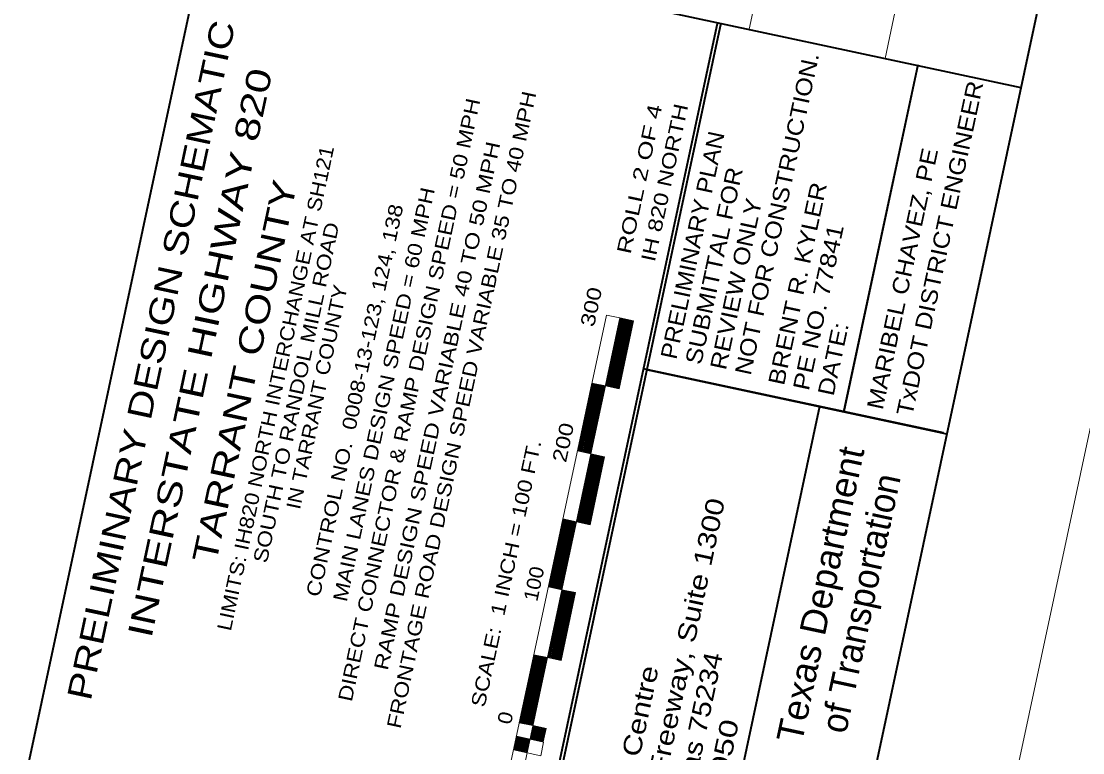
# Model space of a CAD drawing. Extents: x 2363411 to 2369126, y 6976878 to 6988319.
# Drawn here: x 2366272 to 2367036, y 6977474 to 6978000 of the extents above; entities that cross this region are included whole.
import ezdxf
from ezdxf.enums import TextEntityAlignment as Align

# ---------------------------------------------------------------- set-up
doc = ezdxf.new("R2010")
doc.units = 0
doc.header["$LTSCALE"] = 2
for name, color, linetype, lineweight in [('40', 7, 'Continuous', 13), ('62', 7, 'Continuous', 13), ('63', 7, 'Continuous', 13)]:
    doc.layers.add(name, color=color, linetype=linetype, lineweight=lineweight)
doc.layers.add('61', color=7, linetype='Continuous')

msp = doc.modelspace()

# ---------------------------------------------------------------- linework, layer by layer
at = {"layer": '40'}
for p, q in [((2368675.884, 6986794.415), (2366795.645, 6977994.623)), ((2368773.68, 6986773.519), (2366893.442, 6977973.727))]:
    msp.add_line(p, q, dxfattribs=at)
at = {"layer": '62'}
for p, q in [((2369126.202, 6987466.173), (2366932.108, 6977197.487)), ((2366609.253, 6977397.699), (2366692.845, 6977788.923)), ((2366619.034, 6977395.61), (2366702.626, 6977786.834)), ((2366692.438, 6977737.874), (2366702.888, 6977786.777)), ((2366692.845, 6977788.923), (2366702.626, 6977786.834)), ((2366692.927, 6977737.77), (2366703.376, 6977786.672)), ((2366693.416, 6977737.664), (2366703.865, 6977786.569)), ((2366693.905, 6977737.56), (2366704.355, 6977786.463)), ((2366694.393, 6977737.456), (2366704.843, 6977786.359)), ((2366694.883, 6977737.351), (2366705.332, 6977786.254)), ((2366695.372, 6977737.246), (2366705.82, 6977786.15)), ((2366695.861, 6977737.142), (2366706.309, 6977786.047)), ((2366696.35, 6977737.038), (2366706.799, 6977785.941)), ((2366696.839, 6977736.934), (2366707.287, 6977785.837)), ((2366697.328, 6977736.83), (2366707.777, 6977785.733)), ((2366697.817, 6977736.725), (2366708.266, 6977785.628)), ((2366698.305, 6977736.619), (2366708.755, 6977785.524)), ((2366698.795, 6977736.515), (2366709.244, 6977785.418)), ((2366699.285, 6977736.41), (2366709.733, 6977785.314)), ((2366699.774, 6977736.306), (2366710.223, 6977785.209)), ((2366700.263, 6977736.201), (2366710.712, 6977785.105)), ((2366700.752, 6977736.097), (2366711.201, 6977785.001)), ((2366701.241, 6977735.993), (2366711.69, 6977784.896)), ((2366701.73, 6977735.889), (2366712.179, 6977784.792)), ((2366702.626, 6977786.834), (2366712.407, 6977784.744)), ((2366672.33, 6977691.036), (2366682.778, 6977739.937)), ((2366672.82, 6977690.931), (2366683.269, 6977739.834)), ((2366673.309, 6977690.827), (2366683.757, 6977739.728)), ((2366673.796, 6977690.721), (2366684.247, 6977739.625)), ((2366674.285, 6977690.617), (2366684.736, 6977739.519)), ((2366674.775, 6977690.512), (2366685.224, 6977739.415)), ((2366675.265, 6977690.409), (2366685.714, 6977739.311)), ((2366675.753, 6977690.303), (2366686.202, 6977739.206)), ((2366676.242, 6977690.199), (2366686.691, 6977739.101)), ((2366676.732, 6977690.095), (2366687.181, 6977738.997)), ((2366677.22, 6977689.99), (2366687.67, 6977738.893)), ((2366677.71, 6977689.886), (2366688.158, 6977738.789)), ((2366678.198, 6977689.781), (2366688.647, 6977738.683)), ((2366678.688, 6977689.677), (2366689.135, 6977738.579)), ((2366679.176, 6977689.572), (2366689.625, 6977738.474)), ((2366679.665, 6977689.467), (2366690.114, 6977738.371)), ((2366680.154, 6977689.364), (2366690.602, 6977738.267)), ((2366680.643, 6977689.258), (2366691.092, 6977738.161)), ((2366681.132, 6977689.155), (2366691.581, 6977738.057)), ((2366681.621, 6977689.05), (2366692.07, 6977737.952)), ((2366682.396, 6977740.019), (2366692.176, 6977737.929)), ((2366692.176, 6977737.929), (2366701.957, 6977735.839)), ((2366671.947, 6977691.118), (2366681.728, 6977689.028)), ((2366671.661, 6977640.042), (2366682.11, 6977688.944)), ((2366672.15, 6977639.938), (2366682.599, 6977688.841)), ((2366672.639, 6977639.833), (2366683.088, 6977688.736)), ((2366673.128, 6977639.728), (2366683.577, 6977688.633)), ((2366673.617, 6977639.625), (2366684.066, 6977688.527)), ((2366674.106, 6977639.519), (2366684.554, 6977688.423)), ((2366674.595, 6977639.415), (2366685.043, 6977688.319)), ((2366675.084, 6977639.31), (2366685.532, 6977688.214)), ((2366675.573, 6977639.206), (2366686.021, 6977688.11)), ((2366676.062, 6977639.102), (2366686.511, 6977688.005)), ((2366676.551, 6977638.997), (2366686.999, 6977687.9)), ((2366677.04, 6977638.893), (2366687.488, 6977687.797)), ((2366677.53, 6977638.788), (2366687.978, 6977687.691)), ((2366678.02, 6977638.684), (2366688.468, 6977687.588)), ((2366678.508, 6977638.579), (2366688.957, 6977687.482)), ((2366678.997, 6977638.474), (2366689.446, 6977687.378)), ((2366679.486, 6977638.37), (2366689.934, 6977687.273)), ((2366679.975, 6977638.265), (2366690.424, 6977687.169)), ((2366680.464, 6977638.162), (2366690.913, 6977687.065)), ((2366680.952, 6977638.057), (2366691.402, 6977686.96)), ((2366681.728, 6977689.028), (2366691.508, 6977686.937)), ((2366651.334, 6977593.251), (2366661.783, 6977642.152)), ((2366651.823, 6977593.146), (2366662.272, 6977642.048)), ((2366652.313, 6977593.042), (2366662.761, 6977641.944)), ((2366652.803, 6977592.936), (2366663.251, 6977641.839)), ((2366653.291, 6977592.832), (2366663.74, 6977641.735)), ((2366653.78, 6977592.727), (2366664.229, 6977641.63)), ((2366654.269, 6977592.623), (2366664.718, 6977641.525)), ((2366654.757, 6977592.52), (2366665.206, 6977641.421)), ((2366655.247, 6977592.414), (2366665.695, 6977641.316)), ((2366655.736, 6977592.31), (2366666.185, 6977641.213)), ((2366656.224, 6977592.206), (2366666.673, 6977641.107)), ((2366656.713, 6977592.101), (2366667.163, 6977641.004)), ((2366657.202, 6977591.996), (2366667.652, 6977640.899)), ((2366657.691, 6977591.891), (2366668.14, 6977640.794)), ((2366658.181, 6977591.788), (2366668.63, 6977640.69)), ((2366658.669, 6977591.684), (2366669.118, 6977640.585)), ((2366659.158, 6977591.578), (2366669.607, 6977640.48)), ((2366659.648, 6977591.475), (2366670.096, 6977640.376)), ((2366660.136, 6977591.369), (2366670.585, 6977640.271)), ((2366660.626, 6977591.266), (2366671.075, 6977640.168)), ((2366661.498, 6977642.214), (2366671.279, 6977640.123)), ((2366671.279, 6977640.123), (2366681.059, 6977638.033)), ((2366650.759, 6977542.238), (2366661.208, 6977591.14)), ((2366651.049, 6977593.311), (2366660.83, 6977591.221)), ((2366651.247, 6977542.133), (2366661.697, 6977591.036)), ((2366651.737, 6977542.028), (2366662.187, 6977590.931)), ((2366652.225, 6977541.923), (2366662.675, 6977590.827)), ((2366652.715, 6977541.819), (2366663.164, 6977590.723)), ((2366660.83, 6977591.221), (2366670.61, 6977589.131)), ((2366653.204, 6977541.714), (2366663.654, 6977590.618)), ((2366653.692, 6977541.61), (2366664.141, 6977590.513)), ((2366654.182, 6977541.506), (2366664.631, 6977590.409)), ((2366654.671, 6977541.402), (2366665.119, 6977590.304)), ((2366655.16, 6977541.296), (2366665.608, 6977590.201)), ((2366655.649, 6977541.193), (2366666.098, 6977590.096)), ((2366656.137, 6977541.088), (2366666.586, 6977589.992)), ((2366656.627, 6977540.983), (2366667.076, 6977589.886)), ((2366657.117, 6977540.878), (2366667.565, 6977589.782)), ((2366657.606, 6977540.774), (2366668.054, 6977589.678)), ((2366658.095, 6977540.669), (2366668.544, 6977589.573)), ((2366658.584, 6977540.565), (2366669.032, 6977589.468)), ((2366659.074, 6977540.461), (2366669.522, 6977589.364)), ((2366659.562, 6977540.357), (2366670.011, 6977589.259)), ((2366660.051, 6977540.252), (2366670.5, 6977589.156)), ((2366630.504, 6977495.429), (2366640.952, 6977544.332)), ((2366630.992, 6977495.325), (2366641.441, 6977544.229)), ((2366631.482, 6977495.221), (2366641.931, 6977544.123)), ((2366631.971, 6977495.117), (2366642.42, 6977544.019)), ((2366632.459, 6977495.012), (2366642.909, 6977543.914)), ((2366632.949, 6977494.907), (2366643.399, 6977543.81)), ((2366633.438, 6977494.803), (2366643.887, 6977543.706)), ((2366633.926, 6977494.698), (2366644.377, 6977543.6)), ((2366634.416, 6977494.595), (2366644.865, 6977543.496)), ((2366634.905, 6977494.49), (2366645.354, 6977543.392)), ((2366635.394, 6977494.385), (2366645.844, 6977543.287)), ((2366635.883, 6977494.281), (2366646.332, 6977543.183)), ((2366636.372, 6977494.177), (2366646.822, 6977543.078)), ((2366636.861, 6977494.071), (2366647.31, 6977542.975)), ((2366637.35, 6977493.967), (2366647.799, 6977542.869)), ((2366637.839, 6977493.862), (2366648.289, 6977542.765)), ((2366638.328, 6977493.758), (2366648.777, 6977542.66)), ((2366638.817, 6977493.653), (2366649.265, 6977542.557)), ((2366639.306, 6977493.55), (2366649.755, 6977542.452)), ((2366639.795, 6977493.445), (2366650.243, 6977542.347)), ((2366640.6, 6977544.407), (2366650.382, 6977542.318)), ((2366650.382, 6977542.318), (2366660.161, 6977540.228)), ((2366630.151, 6977495.506), (2366639.932, 6977493.415)), ((2366638.036, 6977483.593), (2366640.126, 6977493.375)), ((2366638.525, 6977483.49), (2366640.616, 6977493.27)), ((2366639.014, 6977483.384), (2366641.103, 6977493.166)), ((2366639.503, 6977483.28), (2366641.592, 6977493.062)), ((2366639.931, 6977493.416), (2366649.713, 6977491.326)), ((2366639.932, 6977493.415), (2366649.712, 6977491.326)), ((2366639.992, 6977483.175), (2366642.082, 6977492.957)), ((2366640.481, 6977483.071), (2366642.57, 6977492.852)), ((2366640.97, 6977482.967), (2366643.06, 6977492.748)), ((2366641.459, 6977482.862), (2366643.549, 6977492.643)), ((2366641.947, 6977482.757), (2366644.038, 6977492.54)), ((2366642.437, 6977482.652), (2366644.527, 6977492.435)), ((2366642.925, 6977482.547), (2366645.015, 6977492.33)), ((2366643.414, 6977482.444), (2366645.504, 6977492.225)), ((2366643.903, 6977482.339), (2366645.992, 6977492.121)), ((2366644.392, 6977482.235), (2366646.482, 6977492.018)), ((2366644.882, 6977482.13), (2366646.972, 6977491.912)), ((2366645.37, 6977482.026), (2366647.46, 6977491.807)), ((2366645.86, 6977481.922), (2366647.95, 6977491.703)), ((2366646.348, 6977481.817), (2366648.439, 6977491.598)), ((2366646.837, 6977481.712), (2366648.927, 6977491.494)), ((2366647.327, 6977481.608), (2366649.417, 6977491.389)), ((2366626.165, 6977475.903), (2366628.254, 6977485.684)), ((2366626.654, 6977475.798), (2366628.744, 6977485.578)), ((2366627.145, 6977475.693), (2366629.234, 6977485.475)), ((2366627.633, 6977475.589), (2366629.722, 6977485.369)), ((2366628.061, 6977485.725), (2366637.841, 6977483.635)), ((2366628.122, 6977475.485), (2366630.212, 6977485.266)), ((2366628.612, 6977475.38), (2366630.701, 6977485.161)), ((2366629.1, 6977475.275), (2366631.19, 6977485.056)), ((2366629.589, 6977475.171), (2366631.679, 6977484.951)), ((2366630.077, 6977475.066), (2366632.167, 6977484.847)), ((2366630.566, 6977474.963), (2366632.657, 6977484.742)), ((2366631.056, 6977474.858), (2366633.146, 6977484.638)), ((2366631.544, 6977474.753), (2366633.636, 6977484.534)), ((2366632.034, 6977474.649), (2366634.124, 6977484.43)), ((2366632.523, 6977474.545), (2366634.614, 6977484.324)), ((2366633.011, 6977474.44), (2366635.102, 6977484.22)), ((2366633.501, 6977474.335), (2366635.591, 6977484.115)), ((2366633.989, 6977474.23), (2366636.081, 6977484.011)), ((2366634.479, 6977474.126), (2366636.569, 6977483.906)), ((2366634.968, 6977474.021), (2366637.058, 6977483.803)), ((2366635.457, 6977473.918), (2366637.547, 6977483.698)), ((2366637.841, 6977483.636), (2366647.622, 6977481.547)), ((2366637.842, 6977483.634), (2366647.623, 6977481.545)), ((2366625.972, 6977475.943), (2366635.752, 6977473.854))]:
    msp.add_line(p, q, dxfattribs=at)
at = {"layer": '62', "lineweight": 40}
msp.add_line((2369007.509, 6987389.272), (2366855.207, 6977316.18), dxfattribs=at)
at = {"layer": '62', "lineweight": 35}
for p, q in [((2366271.525, 6977440.894), (2366407.557, 6978077.545)), ((2366407.557, 6978077.545), (2366991.239, 6977952.831)), ((2366772.778, 6977999.891), (2366636.741, 6977363.211)), ((2366917.067, 6977969.062), (2366863.743, 6977719.498)), ((2366935.571, 6977704.151), (2366719.454, 6977750.326)), ((2366846.367, 6977723.21), (2366763.652, 6977336.094))]:
    msp.add_line(p, q, dxfattribs=at)
at = {"layer": '62'}
for points in [[(2366701.957, 6977735.839), (2366712.407, 6977784.744), (2366702.626, 6977786.834), (2366692.176, 6977737.929)], [(2366681.728, 6977689.028), (2366692.176, 6977737.929), (2366682.396, 6977740.019), (2366671.947, 6977691.118)], [(2366681.059, 6977638.033), (2366691.508, 6977686.937), (2366681.728, 6977689.028), (2366671.279, 6977640.123)], [(2366660.83, 6977591.221), (2366671.279, 6977640.123), (2366661.498, 6977642.214), (2366651.049, 6977593.311)], [(2366660.161, 6977540.228), (2366670.61, 6977589.131), (2366660.83, 6977591.221), (2366650.382, 6977542.318)], [(2366639.932, 6977493.415), (2366650.382, 6977542.318), (2366640.6, 6977544.407), (2366630.151, 6977495.506)], [(2366645.533, 6977471.764), (2366647.623, 6977481.545), (2366628.061, 6977485.725), (2366625.972, 6977475.943)]]:
    msp.add_lwpolyline(points, close=True, dxfattribs=at)
at = {"layer": '63'}
for p, q in [((2369126.202, 6987466.173), (2366932.108, 6977197.487)), ((2368675.884, 6986794.415), (2366795.645, 6977994.623)), ((2368773.68, 6986773.519), (2366893.442, 6977973.727))]:
    msp.add_line(p, q, dxfattribs=at)
at = {"layer": '63', "lineweight": 40}
msp.add_line((2369007.509, 6987389.272), (2366855.207, 6977316.18), dxfattribs=at)
at = {"layer": '63', "lineweight": 35}
for p, q in [((2366407.557, 6978077.545), (2366991.239, 6977952.831)), ((2366775.132, 6977999.006), (2366639.1, 6977362.355)), ((2366917.067, 6977969.062), (2366863.653, 6977719.076)), ((2366937.917, 6977703.278), (2366721.81, 6977749.451))]:
    msp.add_line(p, q, dxfattribs=at)

# ---------------------------------------------------------------- texts
at = {"layer": '61'}
for s, width, p in [('LIMITS: IH820 NORTH INTERCHANGE AT SH121', 1.15, (2366459.639, 6977735.272)), ('SOUTH TO RANDOL MILL ROAD', 1.2, (2366474.505, 6977732.097)), ('IN TARRANT COUNTY', 1.15, (2366489.37, 6977728.92))]:
    msp.add_text(s, height=10.2, rotation=77.939, dxfattribs=dict(at, width=width)).set_placement(p, align=Align.CENTER)
at = {"layer": '62'}
for s, height, width, p in [('PRELIMINARY DESIGN SCHEMATIC', 17.5, 1.25, (2366321.505, 6977510.622)), ('INTERSTATE HIGHWAY 820', 17.5, 1.35, (2366365.169, 6977555.695)), ('TxDOT DISTRICT ENGINEER', 11.74, 1.15, (2366912.995, 6977715.626)), ('MARIBEL CHAVEZ, PE', 11.74, 1.15, (2366891.734, 6977720.168)), ('TARRANT COUNTY', 17.5, 1.3, (2366411.681, 6977609.434)), ('BRENT R. KYLER', 11.74, 1.15, (2366820.669, 6977737.729)), ('CONTROL NO.  0008-13-123, 124, 138', 10.2, 1.2, (2366486.475, 6977585.463)), ('PE NO. 77841', 11.74, 1.2, (2366838.504, 6977733.918)), ('DATE: ', 11.74, 1.15, (2366856.337, 6977730.109)), ('3010 LBJ Freeway, Suite 1300', 13.22, 1.25, (2366715.218, 6977359.911)), ('Dallas, Texas 75234', 13.22, 1.2, (2366736.291, 6977355.409)), ('Graystone Centre', 13.22, 1.25, (2366694.145, 6977364.414)), ('972-406-6950', 13.22, 1.35, (2366757.364, 6977350.906))]:
    msp.add_text(s, height=height, rotation=77.939, dxfattribs=dict(at, width=width)).set_placement(p)
for s, height, width, p in [('DIRECT CONNECTOR & RAMP DESIGN SPEED = 50 MPH', 10.2, 1.2, (2366555.801, 6977726.878)), ('FRONTAGE ROAD DESIGN SPEED VARIABLE 35 TO 40 MPH', 10.2, 1.2, (2366593.51, 6977719.718)), ('ROLL 2 OF 4', 10.2, 1.35, (2366721.619, 6977885.83)), ('IH 820 NORTH', 10.2, 1.25, (2366739.733, 6977883.236)), ('RAMP DESIGN SPEED VARIABLE 40 TO 50 MPH', 10.2, 1.25, (2366575.923, 6977722.579)), ('MAIN LANES DESIGN SPEED = 60 MPH', 10.2, 1.2, (2366537.633, 6977730.762)), ('300', 10.2, 1.25, (2366686.886, 6977793.782)), ('200', 10.2, 1.25, (2366666.691, 6977696.157)), ('SCALE:  1 INCH = 100 FT.', 10.2, 1.2, (2366625.633, 6977601.875)), ('Texas Department', 18.76, 1.05, (2366856.112, 6977585.826)), ('100', 10.2, 1.1, (2366645.642, 6977594.47)), ('0', 10.2, 1.15, (2366625.01, 6977497.939))]:
    msp.add_text(s, height=height, rotation=77.939, dxfattribs=dict(at, width=width)).set_placement(p, align=Align.CENTER)
msp.add_text('of Transportation', height=18.76, rotation=77.939, dxfattribs=at).set_placement((2366885.096, 6977579.561), align=Align.CENTER)
at = {"layer": '63'}
for s, width, p in [('NOT FOR CONSTRUCTION.', 1.15, (2366796.674, 6977744.98)), ('PRELIMINARY PLAN', 1.1, (2366743.156, 6977756.415)), ('SUBMITTAL FOR', 1.15, (2366760.995, 6977752.603)), ('REVIEW ONLY', 1.15, (2366778.834, 6977748.791))]:
    msp.add_text(s, height=11.74, rotation=77.939, dxfattribs=dict(at, width=width)).set_placement(p)
at = {"layer": '63', "width": 1.05}
msp.add_text('Texas Department', height=18.76, rotation=77.939, dxfattribs=at).set_placement((2366856.112, 6977585.826), align=Align.CENTER)
at = {"layer": '63'}
msp.add_text('of Transportation', height=18.76, rotation=77.939, dxfattribs=at).set_placement((2366885.096, 6977579.561), align=Align.CENTER)

doc.saveas('drawing.dxf')
